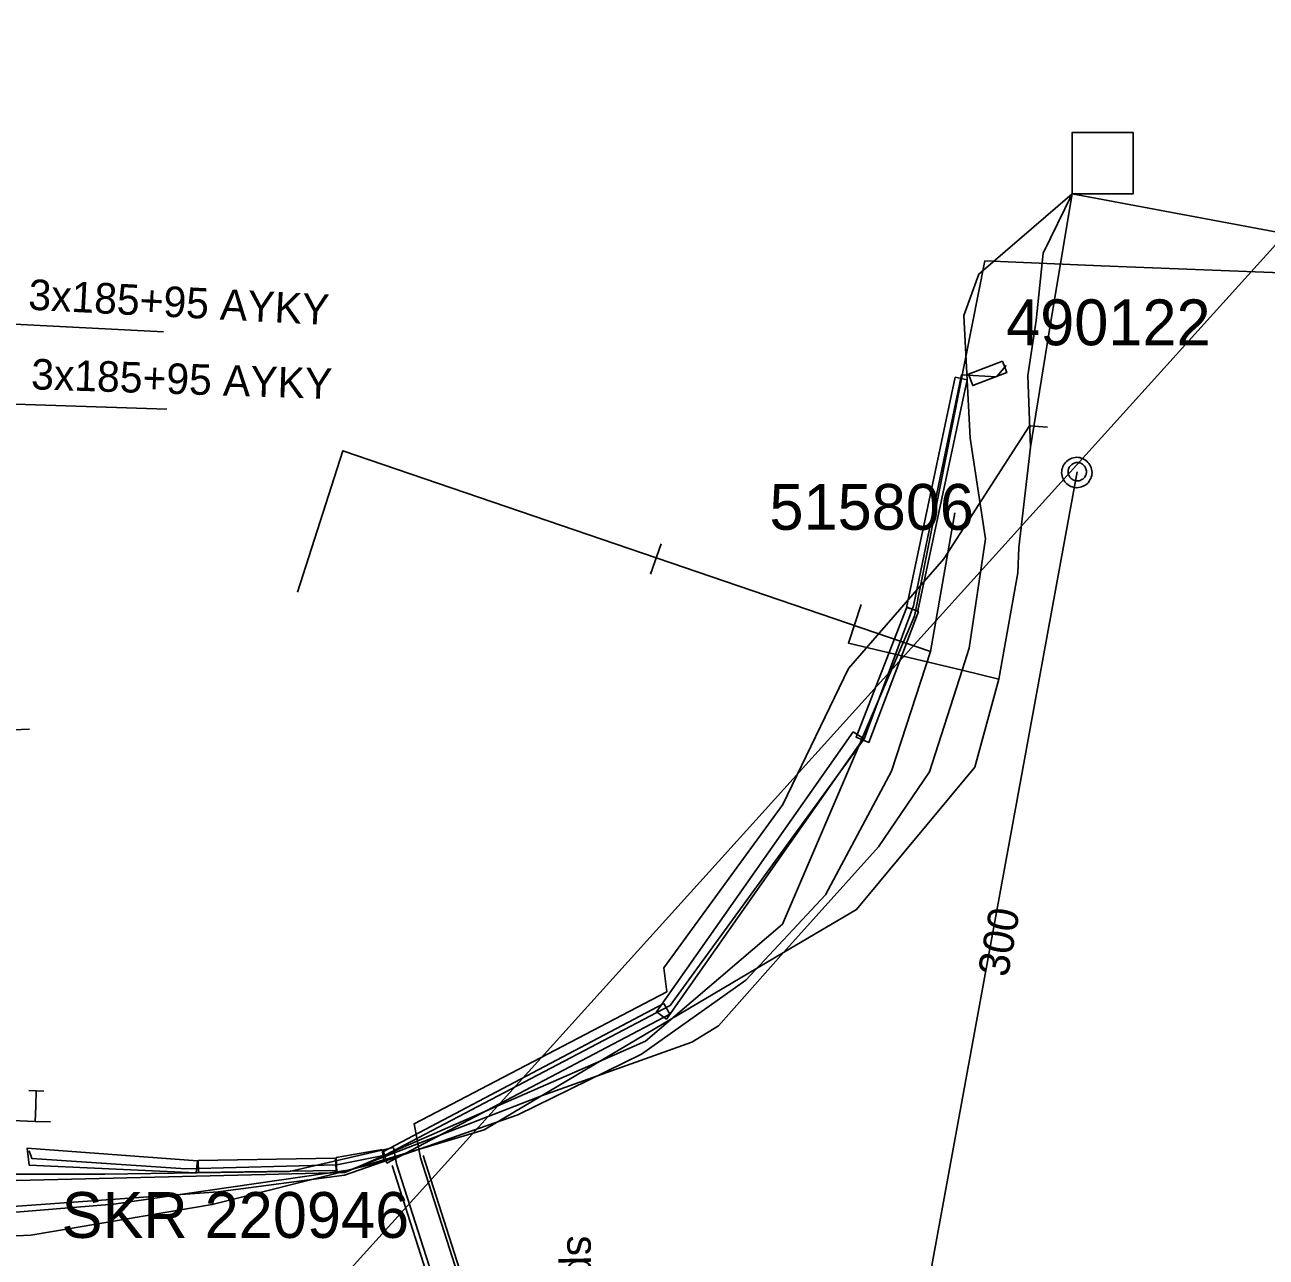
# Model space of a CAD drawing. Extents: x -746464 to -745690, y -1051581 to -1049993.
# Drawn here: x -745922.01 to -745881.39, y -1051030.03 to -1050989.69 of the extents above; entities that cross this region are included whole.
import ezdxf

# ---------------------------------------------------------------- set-up
doc = ezdxf.new("R2010")
doc.units = 0
for name, color, linetype in [('04_CETIN_kabelovody', 7, 'Continuous'), ('04_CETIN_neprovozovane', 7, 'Continuous'), ('04_CETIN_NN', 7, 'Continuous'), ('04_CETIN_radiove site', 7, 'Continuous'), ('04_CETIN_sdelovaci_podzem', 7, 'Continuous'), ('45_Eltodo_chranicka', 7, 'Continuous'), ('45_Eltodo_popisy', 7, 'Continuous'), ('45_Eltodo_vedeni_NN_zemni', 7, 'Continuous'), ('51_PVaK_kanal_NEPROVOZUJE PVK_overena poloha', 7, 'Continuous'), ('51_PVaK_kanal_objekty', 7, 'Continuous'), ('51_PVaK_kanal_popisy', 7, 'Continuous'), ('51_PVaK_vodovod_chranicky_objekty', 7, 'Continuous'), ('51_PVaK_vodovod_zruseno_neoverena poloha', 7, 'Continuous'), ('55_PREdi_chranicky', 7, 'Continuous'), ('55_PREdi_NN', 7, 'Continuous'), ('55_PREdi_NN_popisy', 7, 'Continuous'), ('55_PREdi_NN_pripojovaci_misto', 7, 'Continuous')]:
    doc.layers.add(name, color=color, linetype=linetype)

msp = doc.modelspace()

# ---------------------------------------------------------------- linework, layer by layer
at = {"layer": '04_CETIN_kabelovody'}
msp.add_lwpolyline([(-745887.74, -1050995.22), (-745885.74, -1050995.22), (-745885.74, -1050993.22), (-745887.74, -1050993.22)], close=True, dxfattribs=at)
at = {"layer": '04_CETIN_neprovozovane'}
for points in [[(-745890.6, -1050997.42), (-745892.9, -1051009.05)], [(-745849.24, -1050999.11), (-745849.81, -1050999.02), (-745886.79, -1050997.58), (-745890.6, -1050997.42)]]:
    msp.add_lwpolyline(points, dxfattribs=at)
at = {"layer": '04_CETIN_NN'}
for points in [[(-745889.19, -1051001.17), (-745888.92, -1050999.37), (-745888.69, -1050997.16), (-745887.74, -1050995.22)], [(-745889.1, -1051003.51), (-745888.45, -1050999.47), (-745887.74, -1050995.22)], [(-745887.74, -1050995.22), (-745849.18, -1051002.43), (-745848.05, -1051003.92)], [(-745889.1, -1051003.51), (-745889.19, -1051001.17)], [(-745889.48, -1051006.8), (-745889.1, -1051003.51)], [(-745889.52, -1051007.63), (-745889.48, -1051006.8)], [(-745890.14, -1051011.11), (-745889.52, -1051007.63)], [(-745890.14, -1051011.11), (-745890.92, -1051013.99), (-745894.79, -1051018.65), (-745897.18, -1051020.06)], [(-745897.18, -1051020.06), (-745905.1, -1051024.75)], [(-745905.1, -1051024.75), (-745906.98, -1051025.86), (-745911.36, -1051027.17)], [(-745911.36, -1051027.17), (-745915.88, -1051028.31), (-745921.82, -1051029.31), (-745926.98, -1051029.54), (-745928.18, -1051029.48), (-745929.56, -1051029.35)]]:
    msp.add_lwpolyline(points, dxfattribs=at)
at = {"layer": '04_CETIN_radiove site'}
msp.add_line((-745690.053, -1050785.364), (-746408.207, -1051580.571), dxfattribs=at)
at = {"layer": '04_CETIN_sdelovaci_podzem'}
for points in [[(-745890.57, -1051006.52), (-745891.07, -1051003.22), (-745891.28, -1050999.2), (-745890.79, -1050997.85), (-745887.74, -1050995.22)], [(-745889.19, -1051001.17), (-745888.92, -1050999.37), (-745888.69, -1050997.16), (-745887.74, -1050995.22)], [(-745889.1, -1051003.51), (-745888.45, -1050999.47), (-745887.74, -1050995.22)], [(-745888.92, -1050999.37), (-745888.69, -1050997.16), (-745887.74, -1050995.22)], [(-745888.45, -1050999.47), (-745887.74, -1050995.22)], [(-745887.74, -1050995.22), (-745849.18, -1051002.43)], [(-745887.74, -1050995.22), (-745849.18, -1051002.43), (-745848.05, -1051003.92)], [(-745886.79, -1050997.58), (-745849.81, -1050999.02)], [(-745889.1, -1051003.51), (-745889.19, -1051001.17)], [(-745889.48, -1051006.8), (-745889.1, -1051003.51)], [(-745891.11, -1051010.1), (-745890.57, -1051006.52)], [(-745889.52, -1051007.63), (-745889.48, -1051006.8)], [(-745890.14, -1051011.11), (-745889.52, -1051007.63)], [(-745894.64, -1051008.66), (-745895.06, -1051009.93), (-745891.34, -1051010.82), (-745890.14, -1051011.11)], [(-745892.9, -1051009.05), (-745897.22, -1051019.13)], [(-745897.18, -1051020.06), (-745894.08, -1051016.6), (-745892.41, -1051014.14), (-745891.34, -1051010.82), (-745891.11, -1051010.1)], [(-745890.14, -1051011.11), (-745890.92, -1051013.99), (-745894.79, -1051018.65), (-745897.18, -1051020.06)], [(-745931.5, -1051013.15), (-745921.86, -1051012.75)], [(-745897.22, -1051019.13), (-745901.7, -1051022.96), (-745902.71, -1051023.41)], [(-745897.18, -1051020.06), (-745905.1, -1051024.75)], [(-745905.1, -1051024.75), (-745900.18, -1051022.99), (-745899.31, -1051022.46), (-745897.18, -1051020.06)], [(-745902.71, -1051023.41), (-745911.03, -1051027.04), (-745911.54, -1051027.26), (-745914.14, -1051027.32)], [(-745905.1, -1051024.75), (-745906.98, -1051025.86), (-745911.36, -1051027.17)], [(-745911.36, -1051027.17), (-745905.1, -1051024.75)], [(-745911.36, -1051027.17), (-745915.88, -1051028.31), (-745921.82, -1051029.31), (-745926.98, -1051029.54), (-745928.18, -1051029.48), (-745929.56, -1051029.35)], [(-745929.56, -1051029.35), (-745927.3, -1051028.72), (-745926.03, -1051028.74), (-745922.44, -1051028.57), (-745919.11, -1051028.29), (-745911.36, -1051027.17)], [(-745914.14, -1051027.32), (-745922.3, -1051027.52)]]:
    msp.add_lwpolyline(points, dxfattribs=at)
at = {"layer": '45_Eltodo_chranicka'}
for points in [[(-745908.975, -1051026.698), (-745905.831, -1051036.531)], [(-745909.996, -1051027.025), (-745906.852, -1051036.858)]]:
    msp.add_lwpolyline(points, dxfattribs=at)
at = {"layer": '45_Eltodo_vedeni_NN_zemni'}
for points in [[(-745921.869, -1051026.549), (-745921.789, -1051026.799), (-745916.739, -1051027.139), (-745911.799, -1051027.01), (-745910.219, -1051026.69), (-745900.89, -1051021.79), (-745894.549, -1051013.06), (-745892.929, -1051008.71), (-745891.359, -1051001.149), (-745890.21, -1051001.21), (-745889.9, -1051000.839)], [(-745905.11, -1051036.36), (-745905.438, -1051036.036), (-745906.041, -1051036.232), (-745909.063, -1051026.783), (-745909.273, -1051025.662), (-745901.001, -1051021.341), (-745901.101, -1051020.561), (-745897.211, -1051015.211), (-745895.061, -1051010.761), (-745891.941, -1051007.171), (-745889.131, -1051002.821), (-745888.54, -1051002.86)], [(-745926.41, -1051029.3), (-745926.36, -1051027.15), (-745922.39, -1051027.31), (-745919.39, -1051027.31), (-745913.35, -1051027.22), (-745909.95, -1051026.44), (-745909.848, -1051026.978), (-745906.57, -1051037.229), (-745905.305, -1051036.874), (-745905.11, -1051036.36)]]:
    msp.add_lwpolyline(points, dxfattribs=at)
at = {"layer": '51_PVaK_kanal_NEPROVOZUJE PVK_overena poloha'}
msp.add_line((-745887.57, -1051004.32), (-745894.69, -1051043.15), dxfattribs=at)
at = {"layer": '51_PVaK_kanal_objekty'}
for points in [[(-745887.685, -1051004.837), (-745887.634, -1051004.838), (-745887.585, -1051004.847), (-745887.532, -1051004.838), (-745887.479, -1051004.828), (-745887.426, -1051004.818), (-745887.381, -1051004.797), (-745887.336, -1051004.775), (-745887.288, -1051004.744), (-745887.251, -1051004.711), (-745887.214, -1051004.678), (-745887.184, -1051004.632), (-745887.155, -1051004.587), (-745887.125, -1051004.542), (-745887.115, -1051004.493), (-745887.096, -1051004.446), (-745887.096, -1051004.395), (-745887.086, -1051004.346), (-745887.095, -1051004.293), (-745887.105, -1051004.24), (-745887.115, -1051004.188), (-745887.136, -1051004.142), (-745887.158, -1051004.097), (-745887.189, -1051004.05), (-745887.222, -1051004.013), (-745887.256, -1051003.976), (-745887.301, -1051003.946), (-745887.346, -1051003.917), (-745887.391, -1051003.887), (-745887.44, -1051003.877), (-745887.487, -1051003.857), (-745887.538, -1051003.857), (-745887.587, -1051003.847), (-745887.64, -1051003.857), (-745887.693, -1051003.867), (-745887.746, -1051003.877), (-745887.791, -1051003.898), (-745887.836, -1051003.919), (-745887.883, -1051003.951), (-745887.92, -1051003.984), (-745887.958, -1051004.017), (-745887.987, -1051004.062), (-745888.017, -1051004.107), (-745888.046, -1051004.152), (-745888.056, -1051004.201), (-745888.076, -1051004.248), (-745888.076, -1051004.299), (-745888.086, -1051004.348), (-745888.076, -1051004.401), (-745888.066, -1051004.454), (-745888.057, -1051004.507), (-745888.035, -1051004.552), (-745888.014, -1051004.598), (-745887.982, -1051004.645), (-745887.949, -1051004.682), (-745887.916, -1051004.719), (-745887.871, -1051004.749), (-745887.826, -1051004.778), (-745887.781, -1051004.808), (-745887.732, -1051004.818), (-745887.685, -1051004.837)], [(-745887.629, -1051004.614), (-745887.6, -1051004.62), (-745887.569, -1051004.62), (-745887.539, -1051004.62), (-745887.507, -1051004.614), (-745887.474, -1051004.602), (-745887.447, -1051004.59), (-745887.42, -1051004.577), (-745887.392, -1051004.558), (-745887.369, -1051004.538), (-745887.347, -1051004.518), (-745887.323, -1051004.492), (-745887.306, -1051004.465), (-745887.294, -1051004.437), (-745887.282, -1051004.409), (-745887.276, -1051004.379), (-745887.27, -1051004.35), (-745887.27, -1051004.319), (-745887.27, -1051004.289), (-745887.276, -1051004.257), (-745887.288, -1051004.224), (-745887.3, -1051004.197), (-745887.313, -1051004.17), (-745887.332, -1051004.142), (-745887.352, -1051004.119), (-745887.372, -1051004.097), (-745887.398, -1051004.073), (-745887.425, -1051004.056), (-745887.453, -1051004.044), (-745887.481, -1051004.032), (-745887.511, -1051004.026), (-745887.54, -1051004.02), (-745887.571, -1051004.02), (-745887.601, -1051004.02), (-745887.633, -1051004.026), (-745887.666, -1051004.038), (-745887.693, -1051004.05), (-745887.72, -1051004.063), (-745887.748, -1051004.082), (-745887.771, -1051004.102), (-745887.793, -1051004.122), (-745887.817, -1051004.148), (-745887.834, -1051004.175), (-745887.846, -1051004.203), (-745887.858, -1051004.231), (-745887.864, -1051004.261), (-745887.87, -1051004.29), (-745887.87, -1051004.321), (-745887.87, -1051004.351), (-745887.864, -1051004.383), (-745887.852, -1051004.416), (-745887.84, -1051004.443), (-745887.827, -1051004.47), (-745887.808, -1051004.498), (-745887.788, -1051004.521), (-745887.768, -1051004.543), (-745887.742, -1051004.567), (-745887.715, -1051004.584), (-745887.687, -1051004.596), (-745887.659, -1051004.608), (-745887.629, -1051004.614)]]:
    msp.add_lwpolyline(points, dxfattribs=at)
at = {"layer": '51_PVaK_vodovod_chranicky_objekty'}
msp.add_line((-745901.534, -1051007.675), (-745901.192, -1051006.675), dxfattribs=at)
at = {"layer": '51_PVaK_vodovod_zruseno_neoverena poloha'}
for q in [(-745891.582, -1051005.668), (-745901.349, -1051007.135)]:
    msp.add_line((-745892.371, -1051010.204), q, dxfattribs=at)
for points in [[(-745901.349, -1051007.135), (-745911.61, -1051003.635), (-745913.085, -1051008.265)], [(-745923.793, -1051028.465), (-745915.688, -1051027.886), (-745911.55, -1051027.346), (-745905.884, -1051025.367), (-745901.836, -1051023.389), (-745898.418, -1051020.96), (-745895.81, -1051018.171), (-745893.651, -1051014.124), (-745892.371, -1051010.204)]]:
    msp.add_lwpolyline(points, dxfattribs=at)
at = {"layer": '55_PREdi_chranicky'}
for points in [[(-745890.02, -1051000.7), (-745889.878, -1051001.073), (-745890.988, -1051001.498), (-745891.13, -1051001.124), (-745890.02, -1051000.7)], [(-745891.569, -1051001.228), (-745891.177, -1051001.309), (-745892.793, -1051008.877), (-745893.159, -1051008.767), (-745891.569, -1051001.228)], [(-745893.146, -1051008.757), (-745892.767, -1051008.89), (-745894.391, -1051013.182), (-745894.806, -1051013.011), (-745893.146, -1051008.757)], [(-745894.905, -1051012.829), (-745894.57, -1051013.049), (-745901.015, -1051022.234), (-745901.342, -1051022.003), (-745894.905, -1051012.829)], [(-745901.099, -1051021.725), (-745900.908, -1051022.073), (-745910.162, -1051026.949), (-745910.279, -1051026.574), (-745901.099, -1051021.725)], [(-745916.36, -1051026.875), (-745916.401, -1051027.273), (-745921.87, -1051027.017), (-745921.937, -1051026.462), (-745916.36, -1051026.875)], [(-745910.315, -1051026.506), (-745910.267, -1051026.896), (-745911.803, -1051027.267), (-745911.82, -1051026.768), (-745910.315, -1051026.506)], [(-745911.841, -1051026.791), (-745911.823, -1051027.188), (-745916.33, -1051027.262), (-745916.34, -1051026.863), (-745911.841, -1051026.791)]]:
    msp.add_lwpolyline(points, close=True, dxfattribs=at)
at = {"layer": '55_PREdi_NN'}
for points in [[(-745921.674, -1051025.584), (-745921.654, -1051025.084)], [(-745923.172, -1051025.524), (-745922.673, -1051025.544), (-745922.173, -1051025.564), (-745921.674, -1051025.584), (-745921.174, -1051025.604)]]:
    msp.add_lwpolyline(points, dxfattribs=at)
at = {"layer": '55_PREdi_NN_popisy'}
for points in [[(-745931.625, -1050999.046), (-745926.404, -1050999.281), (-745917.48, -1050999.741)], [(-745932.804, -1051001.795), (-745926.299, -1051001.973), (-745917.368, -1051002.266)]]:
    msp.add_lwpolyline(points, dxfattribs=at)
at = {"layer": '55_PREdi_NN_pripojovaci_misto'}
for p, q in [((-745921.387, -1051024.593), (-745921.886, -1051024.576)), ((-745921.654, -1051025.084), (-745921.637, -1051024.584))]:
    msp.add_line(p, q, dxfattribs=at)

# ---------------------------------------------------------------- texts
at = {"layer": '45_Eltodo_popisy'}
for s, p in [('490122', (-745889.899, -1051000.179)), ('515806', (-745897.644, -1051006.22)), ('SKR 220946', (-745920.81, -1051029.399))]:
    msp.add_text(s, height=1.5, dxfattribs=at).set_placement(p)
at = {"layer": '51_PVaK_kanal_popisy'}
for s, rotation, p in [('300 ', 79.6097, (-745889.847, -1051020.894)), ('sp.', 271.3374, (-745904.267, -1051029.327))]:
    msp.add_text(s, height=1, rotation=rotation, dxfattribs=at).set_placement(p)
at = {"layer": '55_PREdi_NN_popisy'}
for rotation, p in [(357.0493, (-745921.916, -1050999.012)), (358.1261, (-745921.818, -1051001.619))]:
    msp.add_text('3x185+95 AYKY', height=1, rotation=rotation, dxfattribs=at).set_placement(p)

doc.saveas('drawing.dxf')
